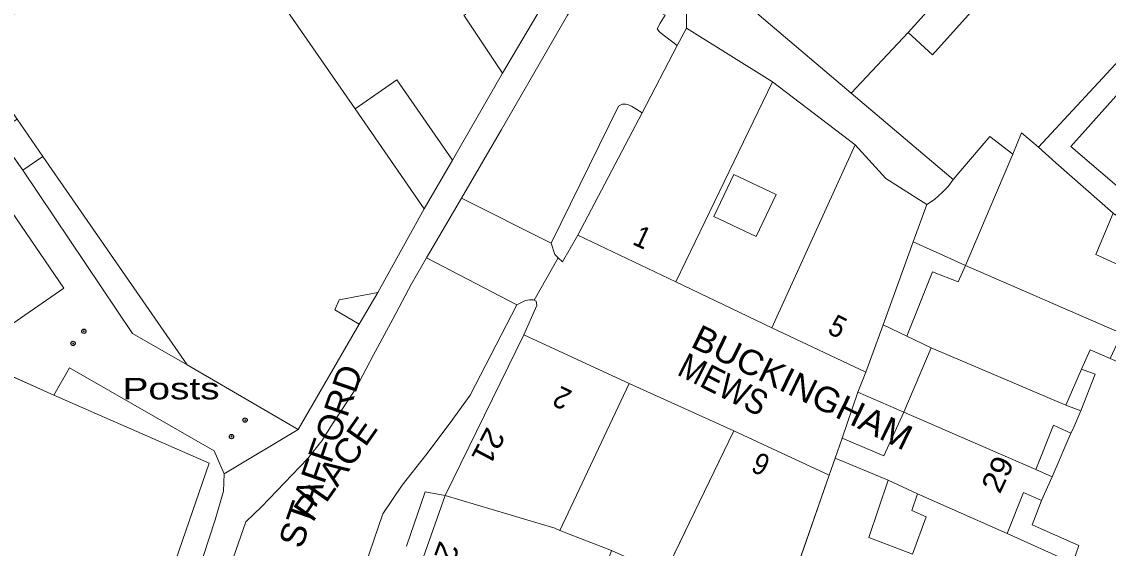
# Model space of a CAD drawing. Extents: x 528790 to 529292, y 179350 to 179856.
# Drawn here: x 529073.1 to 529148.9, y 179462.8 to 179499.5 of the extents above; entities that cross this region are included whole.
import ezdxf

# ---------------------------------------------------------------- set-up
doc = ezdxf.new("R2010")
doc.units = 0
doc.header["$LTSCALE"] = 0.6
doc.header["$PDMODE"] = 32
doc.header["$PDSIZE"] = 0.3
doc.layers.add('1', color=7, linetype='Continuous', lineweight=13)
doc.layers.add('2', color=7, linetype='Continuous', lineweight=13)
doc.layers.add('3', color=7, linetype='Continuous')
doc.layers.add('5', color=7, linetype='Continuous')

msp = doc.modelspace()

# ---------------------------------------------------------------- linework, layer by layer
at = {"layer": '1'}
for points in [[(529146.8, 179512.45), (529154.7, 179521.55), (529151.8, 179524.15), (529145.8, 179529.3), (529145, 179530.05), (529137, 179521.05), (529141.55, 179517.1), (529129.6, 179503.4), (529127.169, 179505.521), (529124.9, 179507.5), (529122.2, 179509.8), (529120.7, 179511.15), (529117.95, 179507.95), (529116.75, 179506.55), (529115.35, 179505), (529119.4, 179501.5), (529120.95, 179503.25), (529124.5, 179500), (529130.929, 179494.567), (529134.9, 179498.8), (529136, 179500)], [(529109, 179500), (529109.35, 179500.6), (529105.55, 179506.3), (529110.55, 179509.6), (529102.9, 179520.85), (529100.55, 179519.25), (529094.1, 179514.85), (529101.27, 179504.213), (529101.65, 179503.65), (529104.05, 179500.05), (529103.9, 179500), (529106.6, 179495.95)], [(529150.25, 179497.55), (529152.55, 179500), (529164.2, 179512.9), (529159.65, 179517), (529154.7, 179521.55), (529146.8, 179512.45), (529148.7, 179510.8), (529139.08, 179500), (529136.6, 179497.25), (529134.9, 179498.8), (529130.929, 179494.567), (529138.05, 179488.55), (529140.6, 179491.55), (529142.2, 179490.3), (529142.8, 179491.8), (529144, 179490.8)], [(529106.6, 179495.95), (529103.9, 179500), (529104.05, 179500.05), (529101.65, 179503.65), (529101.27, 179504.213), (529094.1, 179514.85), (529093.6, 179514.5), (529090.9, 179512.65), (529085.6, 179509), (529091.8, 179500), (529096.316, 179493.479), (529099.225, 179495.494), (529103.106, 179489.891)], [(529146.8, 179512.45), (529136, 179500), (529134.9, 179498.8), (529136.6, 179497.25), (529139.08, 179500), (529148.7, 179510.8)], [(529101.15, 179486.5), (529096.316, 179493.479), (529091.8, 179500), (529085.6, 179509), (529081.6, 179506.25), (529079, 179504.5), (529072.4, 179500), (529069.2, 179497.8), (529072.75, 179492.75), (529074.55, 179490.15), (529084.6, 179475.6), (529092.35, 179471.1), (529096.6, 179478.45), (529094.9, 179479.45), (529095.2, 179480.15), (529097.9, 179480.65)], [(529118.8, 179497.9), (529117.6, 179498.8), (529117.5, 179498.9), (529117.4, 179499.05), (529117.6, 179499.45), (529117.95, 179500), (529113.347, 179502.643), (529112.9, 179502.9), (529111.15, 179500), (529106.544, 179492.033), (529103.74, 179487.23), (529110, 179484.1), (529114.7, 179493.65), (529114.95, 179493.8), (529115.2, 179493.8), (529115.4, 179493.75), (529115.6, 179493.65), (529116.35, 179493.2)], [(529136.75, 179487.15), (529137.25, 179487.6), (529137.7, 179488.05), (529138.05, 179488.55), (529130.929, 179494.567), (529124.5, 179500), (529120.95, 179503.25), (529119.4, 179501.5), (529119.43, 179500), (529119.45, 179499.1), (529125.45, 179495.35), (529131.2, 179490.95), (529133.35, 179488.6), (529136.2, 179486.8)], [(529160.208, 179502.44), (529159.4, 179503.3), (529156.9, 179500.8), (529156.05, 179501.7), (529154.4, 179500), (529151.35, 179496.55), (529147.252, 179491.97), (529146.25, 179490.85), (529150.434, 179487.257), (529150.5, 179487.2), (529154.75, 179492.1), (529155.4, 179491.65), (529158.109, 179494.835), (529155.019, 179497.544), (529156.256, 179499.037), (529156.719, 179498.613)], [(529116.35, 179493.2), (529111.85, 179484.65), (529118.7, 179481.4), (529125.45, 179495.35), (529119.45, 179499.1), (529118.8, 179497.9)], [(529076, 179480.95), (529065.43, 179496.435), (529065.393, 179496.49), (529064.927, 179497.167), (529064.02, 179498.482), (529063.936, 179498.604), (529056.817, 179495.648), (529056.998, 179495.376), (529058.999, 179492.375), (529069.7, 179476.6)], [(529080.8, 179477.8), (529073.15, 179489.2), (529071.25, 179491.85), (529067.05, 179498.1), (529065.393, 179496.49), (529065.43, 179496.435), (529076, 179480.95), (529069.7, 179476.6), (529058.999, 179492.375), (529058.82, 179492.05), (529058.05, 179490.65), (529068.4, 179476.25), (529070.95, 179475.45), (529075.3, 179473.5), (529076.4, 179475.4), (529086.5, 179469.6), (529087.2, 179468), (529092.35, 179471.1), (529084.6, 179475.6)], [(529149.4, 179486.1), (529150.5, 179487.2), (529150.434, 179487.257), (529146.25, 179490.85), (529147.252, 179491.97), (529151.35, 179496.55), (529150.25, 179497.55), (529144, 179490.8), (529145.2, 179489.7), (529149.2, 179486.2), (529149.361, 179486.057)], [(529103.106, 179489.891), (529099.225, 179495.494), (529096.316, 179493.479), (529101.15, 179486.5)], [(529131.2, 179490.95), (529125.45, 179495.35), (529118.7, 179481.4), (529125.4, 179478.2)], [(529111.85, 179484.65), (529116.35, 179493.2), (529115.6, 179493.65), (529115.4, 179493.75), (529115.2, 179493.8), (529114.95, 179493.8), (529114.7, 179493.65), (529110, 179484.1), (529110.25, 179483.3), (529110.5, 179483.07), (529110.8, 179482.8)], [(529071.25, 179491.85), (529073.15, 179489.2), (529074.55, 179490.15), (529072.75, 179492.75)], [(529136.2, 179486.8), (529135.25, 179484.2), (529137.11, 179483.36), (529138.9, 179482.55), (529141.06, 179487.63), (529142.2, 179490.3), (529140.6, 179491.55), (529138.05, 179488.55), (529137.7, 179488.05), (529137.25, 179487.6), (529136.75, 179487.15)], [(529144, 179490.8), (529142.8, 179491.8), (529142.2, 179490.3), (529141.06, 179487.63), (529138.9, 179482.55), (529149.8, 179477.8), (529152.259, 179476.764), (529154.55, 179475.8), (529156.35, 179480), (529152.25, 179483.55), (529151.5, 179481.7), (529148, 179483.3), (529149.2, 179486.2), (529145.2, 179489.7)], [(529125.4, 179478.2), (529131.95, 179475.1), (529133.15, 179478.4), (529135.25, 179484.2), (529136.2, 179486.8), (529133.35, 179488.6), (529131.2, 179490.95)], [(529074.55, 179490.15), (529073.15, 179489.2), (529080.8, 179477.8), (529084.6, 179475.6)], [(529121.353, 179485.965), (529124.301, 179484.565), (529125.695, 179487.499), (529122.747, 179488.899)], [(529121.353, 179485.965), (529122.747, 179488.899), (529125.695, 179487.499), (529124.301, 179484.565)], [(529110.5, 179483.07), (529110.25, 179483.3), (529110, 179484.1), (529103.74, 179487.23), (529102.636, 179485.34), (529101.31, 179483.07), (529107.6, 179479.8), (529108.2, 179480.1), (529108.5, 179480.15), (529108.75, 179480.15), (529108.82, 179480.11)], [(529149.2, 179486.2), (529148, 179483.3), (529151.5, 179481.7), (529152.25, 179483.55), (529151.25, 179484.55), (529149.4, 179486.1), (529149.361, 179486.057)], [(529110.8, 179482.8), (529110.5, 179483.07), (529108.82, 179480.11), (529108.95, 179480.05), (529109, 179479.75), (529108.1, 179477.7), (529115.45, 179474.3), (529122.75, 179471), (529129.4, 179467.9), (529129.8, 179469.1), (529130.3, 179470.5), (529131.4, 179473.7), (529131.95, 179475.1), (529125.4, 179478.2), (529118.7, 179481.4), (529111.85, 179484.65)], [(529134.8, 179477.6), (529136.6, 179482.1), (529138.4, 179481.4), (529138.9, 179482.55), (529137.11, 179483.36), (529135.25, 179484.2), (529133.15, 179478.4)], [(529098.25, 179465.2), (529099.6, 179467.2), (529101.25, 179469.3), (529102.95, 179471.55), (529104.35, 179473.5), (529107.6, 179479.8), (529101.31, 179483.07), (529100.25, 179481.25), (529098.95, 179478.8), (529097.6, 179476.3), (529096.35, 179473.9), (529094.8, 179471.55), (529094, 179470.3), (529093, 179469.05), (529089.8, 179465.7), (529088.7, 179464.65), (529072.2, 179417.3), (529072, 179416.9), (529071.7, 179416.55), (529071.39, 179416.36), (529080.46, 179413.16)], [(529149.8, 179477.8), (529138.9, 179482.55), (529138.4, 179481.4), (529136.6, 179482.1), (529134.8, 179477.6), (529136.5, 179476.8), (529145.9, 179472.8), (529147, 179475.3), (529147.6, 179476.65), (529149, 179476.05)], [(529096.6, 179478.45), (529097.9, 179480.65), (529095.2, 179480.15), (529094.9, 179479.45)], [(529133.15, 179478.4), (529131.95, 179475.1), (529131.4, 179473.7), (529134.6, 179472.3), (529136.5, 179476.8), (529134.8, 179477.6)], [(529102.6, 179466.5), (529110.25, 179464.2), (529110.6, 179464.05), (529115.45, 179474.3), (529108.1, 179477.7)], [(529146.95, 179472.4), (529145.9, 179472.8), (529136.5, 179476.8), (529134.6, 179472.3), (529143.8, 179468.3), (529145.05, 179471.4), (529146.25, 179470.85), (529146.4, 179471.1)], [(529155.75, 179465.25), (529152.8, 179466.55), (529155.7, 179473.15), (529153.7, 179474), (529151.472, 179474.972), (529149, 179476.05), (529147.6, 179476.65), (529147, 179475.3), (529147.95, 179474.95), (529146.95, 179472.4), (529146.4, 179471.1), (529146.25, 179470.85), (529144.95, 179467.8), (529144.2, 179466.15), (529143.55, 179464.45), (529146.8, 179463), (529146.4, 179461.8), (529147, 179461.55), (529153.4, 179460.25)], [(529085.75, 179462.3), (529086.55, 179464.8), (529087.15, 179466.8), (529087.2, 179468), (529086.5, 179469.6), (529076.4, 179475.4), (529075.3, 179473.5), (529086.15, 179468.75), (529068.6, 179417.95), (529070.05, 179417.6)], [(529146.95, 179472.4), (529147.95, 179474.95), (529147, 179475.3), (529145.9, 179472.8)], [(529122.75, 179471), (529115.45, 179474.3), (529110.6, 179464.05), (529114.2, 179462.65), (529117.9, 179461)], [(529131.4, 179473.7), (529130.3, 179470.5), (529133.2, 179469.25), (529134.6, 179472.3)], [(529135.55, 179466.6), (529141.8, 179463.85), (529142.95, 179466.7), (529144.2, 179466.15), (529144.95, 179467.8), (529143.8, 179468.3), (529134.6, 179472.3), (529133.2, 179469.25), (529130.3, 179470.5), (529129.8, 179469.1), (529133.5, 179467.55)], [(529117.9, 179461), (529123, 179458.85), (529125.75, 179457.7), (529126.4, 179459.3), (529129.4, 179467.9), (529122.75, 179471)], [(529143.8, 179468.3), (529144.95, 179467.8), (529146.25, 179470.85), (529145.05, 179471.4)], [(529144.6, 179457.15), (529145.35, 179459.1), (529146.35, 179461.8), (529141.8, 179463.85), (529135.55, 179466.6), (529135.15, 179465.45), (529136.15, 179465), (529135.2, 179462.4), (529132.15, 179463.55), (529133.5, 179467.55), (529129.8, 179469.1), (529129.4, 179467.9), (529126.4, 179459.3), (529130.2, 179457.95), (529131.25, 179460.8), (529134.35, 179459.8), (529133.2, 179456.8), (529143.2, 179453.25)], [(529133.5, 179467.55), (529132.15, 179463.55), (529135.2, 179462.4), (529136.15, 179465), (529135.15, 179465.45), (529135.55, 179466.6)], [(529114.2, 179462.65), (529110.6, 179464.05), (529110.25, 179464.2), (529102.6, 179466.5), (529100.8, 179461.35), (529110.4, 179458.15), (529111.6, 179461.5), (529113.55, 179460.8)], [(529145.35, 179459.1), (529146, 179458.95), (529147, 179461.55), (529146.4, 179461.8), (529146.8, 179463), (529143.55, 179464.45), (529144.2, 179466.15), (529142.95, 179466.7), (529141.8, 179463.85), (529146.35, 179461.8)]]:
    msp.add_lwpolyline(points, close=True, dxfattribs=at)
for points in [[(529114.4, 179506.25), (529113.95, 179506.4), (529113.55, 179506.6), (529113.05, 179506.9), (529109.35, 179500.6), (529109, 179500), (529106.6, 179495.95), (529103.106, 179489.891), (529101.15, 179486.5), (529097.9, 179480.65), (529096.6, 179478.45), (529092.35, 179471.1), (529087.2, 179468), (529087.15, 179466.8), (529086.55, 179464.8), (529085.75, 179462.3), (529070.05, 179417.6)], [(529072.2, 179417.3), (529088.7, 179464.65), (529089.8, 179465.7), (529093, 179469.05), (529094, 179470.3), (529094.8, 179471.55), (529096.35, 179473.9), (529097.6, 179476.3), (529098.95, 179478.8), (529100.25, 179481.25), (529101.31, 179483.07), (529102.636, 179485.34), (529103.74, 179487.23), (529106.544, 179492.033), (529111.15, 179500)], [(529117.95, 179500), (529117.6, 179499.45), (529117.4, 179499.05), (529117.5, 179498.9), (529117.6, 179498.8), (529118.8, 179497.9), (529119.45, 179499.1), (529119.43, 179500)], [(529100.8, 179461.35), (529102.6, 179466.5), (529108.1, 179477.7), (529109, 179479.75), (529108.95, 179480.05), (529108.82, 179480.11), (529108.75, 179480.15), (529108.5, 179480.15), (529108.2, 179480.1), (529107.6, 179479.8), (529104.35, 179473.5), (529102.95, 179471.55), (529101.25, 179469.3), (529099.6, 179467.2), (529098.25, 179465.2), (529080.46, 179413.16)], [(529068.6, 179417.95), (529086.15, 179468.75), (529075.3, 179473.5), (529070.95, 179475.45)]]:
    msp.add_lwpolyline(points, dxfattribs=at)
at = {"layer": '2'}
for p, q in [((529119.45, 179499.1), (529118.8, 179497.9)), ((529125.45, 179495.35), (529119.45, 179499.1)), ((529134.9, 179498.8), (529130.929, 179494.567)), ((529118.8, 179497.9), (529116.35, 179493.2)), ((529144, 179490.8), (529150.25, 179497.55)), ((529103.106, 179489.891), (529106.6, 179495.95)), ((529125.45, 179495.35), (529118.7, 179481.4)), ((529131.2, 179490.95), (529125.45, 179495.35)), ((529130.929, 179494.567), (529138.05, 179488.55)), ((529101.15, 179486.5), (529096.316, 179493.479)), ((529116.35, 179493.2), (529111.85, 179484.65)), ((529072.75, 179492.75), (529074.55, 179490.15)), ((529071.25, 179491.85), (529073.15, 179489.2)), ((529131.2, 179490.95), (529125.4, 179478.2)), ((529073.15, 179489.2), (529074.55, 179490.15)), ((529074.55, 179490.15), (529084.6, 179475.6)), ((529101.15, 179486.5), (529103.106, 179489.891)), ((529110, 179484.1), (529103.74, 179487.23)), ((529135.25, 179484.2), (529136.2, 179486.8)), ((529097.9, 179480.65), (529101.15, 179486.5)), ((529111.85, 179484.65), (529110.8, 179482.8)), ((529111.85, 179484.65), (529118.7, 179481.4)), ((529133.15, 179478.4), (529135.25, 179484.2)), ((529101.31, 179483.07), (529107.6, 179479.8)), ((529110.5, 179483.07), (529108.82, 179480.11)), ((529110.8, 179482.8), (529110.5, 179483.07)), ((529138.9, 179482.55), (529149.8, 179477.8)), ((529118.7, 179481.4), (529125.4, 179478.2)), ((529096.6, 179478.45), (529097.9, 179480.65)), ((529109, 179479.75), (529108.1, 179477.7)), ((529092.35, 179471.1), (529096.6, 179478.45)), ((529131.95, 179475.1), (529133.15, 179478.4)), ((529134.8, 179477.6), (529133.15, 179478.4)), ((529108.1, 179477.7), (529102.6, 179466.5)), ((529115.45, 179474.3), (529108.1, 179477.7)), ((529125.4, 179478.2), (529131.95, 179475.1)), ((529136.5, 179476.8), (529134.8, 179477.6)), ((529134.6, 179472.3), (529136.5, 179476.8)), ((529136.5, 179476.8), (529145.9, 179472.8)), ((529075.3, 179473.5), (529070.95, 179475.45)), ((529084.6, 179475.6), (529092.35, 179471.1)), ((529131.4, 179473.7), (529131.95, 179475.1)), ((529147, 179475.3), (529145.9, 179472.8)), ((529115.45, 179474.3), (529110.6, 179464.05)), ((529122.75, 179471), (529115.45, 179474.3)), ((529130.3, 179470.5), (529131.4, 179473.7)), ((529131.4, 179473.7), (529134.6, 179472.3)), ((529145.9, 179472.8), (529146.95, 179472.4)), ((529134.6, 179472.3), (529143.8, 179468.3)), ((529092.35, 179471.1), (529087.2, 179468)), ((529122.75, 179471), (529117.9, 179461)), ((529129.4, 179467.9), (529122.75, 179471)), ((529146.25, 179470.85), (529144.95, 179467.8)), ((529129.8, 179469.1), (529130.3, 179470.5)), ((529129.8, 179469.1), (529129.4, 179467.9)), ((529133.5, 179467.55), (529129.8, 179469.1)), ((529129.4, 179467.9), (529126.4, 179459.3)), ((529143.8, 179468.3), (529144.95, 179467.8)), ((529144.95, 179467.8), (529144.2, 179466.15)), ((529133.5, 179467.55), (529135.55, 179466.6)), ((529100.8, 179461.35), (529102.6, 179466.5)), ((529141.8, 179463.85), (529135.55, 179466.6)), ((529110.6, 179464.05), (529114.2, 179462.65))]:
    msp.add_line(p, q, dxfattribs=at)
for points in [[(529106.6, 179495.95), (529103.9, 179500), (529104.05, 179500.05), (529101.65, 179503.65), (529101.27, 179504.213), (529094.1, 179514.85)], [(529146.8, 179512.45), (529148.7, 179510.8), (529139.08, 179500), (529136.6, 179497.25), (529134.9, 179498.8)], [(529134.9, 179498.8), (529136, 179500), (529146.8, 179512.45)], [(529085.6, 179509), (529091.8, 179500), (529096.316, 179493.479)], [(529103.74, 179487.23), (529106.544, 179492.033), (529111.15, 179500), (529112.9, 179502.9), (529113.347, 179502.643), (529117.95, 179500), (529117.6, 179499.45), (529117.4, 179499.05), (529117.5, 179498.9), (529117.6, 179498.8), (529118.8, 179497.9)], [(529119.4, 179501.5), (529120.95, 179503.25), (529124.5, 179500), (529130.929, 179494.567)], [(529119.45, 179499.1), (529119.43, 179500), (529119.4, 179501.5)], [(529106.6, 179495.95), (529109, 179500), (529109.35, 179500.6)], [(529058.999, 179492.375), (529069.7, 179476.6), (529076, 179480.95), (529065.43, 179496.435), (529065.393, 179496.49)], [(529150.5, 179487.2), (529150.434, 179487.257), (529146.25, 179490.85), (529147.252, 179491.97), (529151.35, 179496.55)], [(529096.316, 179493.479), (529099.225, 179495.494), (529103.106, 179489.891)], [(529110, 179484.1), (529114.7, 179493.65), (529114.95, 179493.8), (529115.2, 179493.8), (529115.4, 179493.75), (529115.6, 179493.65), (529116.35, 179493.2)], [(529138.05, 179488.55), (529140.6, 179491.55), (529142.2, 179490.3)], [(529144, 179490.8), (529142.8, 179491.8), (529142.2, 179490.3)], [(529136.2, 179486.8), (529133.35, 179488.6), (529131.2, 179490.95)], [(529149.2, 179486.2), (529145.2, 179489.7), (529144, 179490.8)], [(529142.2, 179490.3), (529141.06, 179487.63), (529138.9, 179482.55)], [(529073.15, 179489.2), (529080.8, 179477.8), (529084.6, 179475.6)], [(529136.2, 179486.8), (529136.75, 179487.15), (529137.25, 179487.6), (529137.7, 179488.05), (529138.05, 179488.55)], [(529101.31, 179483.07), (529102.636, 179485.34), (529103.74, 179487.23)], [(529152.25, 179483.55), (529151.5, 179481.7), (529148, 179483.3), (529149.2, 179486.2)], [(529110.5, 179483.07), (529110.25, 179483.3), (529110, 179484.1)], [(529135.25, 179484.2), (529137.11, 179483.36), (529138.9, 179482.55)], [(529071.39, 179416.36), (529071.7, 179416.55), (529072, 179416.9), (529072.2, 179417.3), (529088.7, 179464.65), (529089.8, 179465.7), (529093, 179469.05), (529094, 179470.3), (529094.8, 179471.55), (529096.35, 179473.9), (529097.6, 179476.3), (529098.95, 179478.8), (529100.25, 179481.25), (529101.31, 179483.07)], [(529134.8, 179477.6), (529136.6, 179482.1), (529138.4, 179481.4), (529138.9, 179482.55)], [(529096.6, 179478.45), (529094.9, 179479.45), (529095.2, 179480.15), (529097.9, 179480.65)], [(529107.6, 179479.8), (529108.2, 179480.1), (529108.5, 179480.15), (529108.75, 179480.15), (529108.82, 179480.11)], [(529108.82, 179480.11), (529108.95, 179480.05), (529109, 179479.75)], [(529080.46, 179413.16), (529098.25, 179465.2), (529099.6, 179467.2), (529101.25, 179469.3), (529102.95, 179471.55), (529104.35, 179473.5), (529107.6, 179479.8)], [(529149, 179476.05), (529147.6, 179476.65), (529147, 179475.3)], [(529075.3, 179473.5), (529076.4, 179475.4), (529086.5, 179469.6), (529087.2, 179468)], [(529147, 179475.3), (529147.95, 179474.95), (529146.95, 179472.4)], [(529068.6, 179417.95), (529086.15, 179468.75), (529075.3, 179473.5)], [(529146.95, 179472.4), (529146.4, 179471.1), (529146.25, 179470.85)], [(529130.3, 179470.5), (529133.2, 179469.25), (529134.6, 179472.3)], [(529146.25, 179470.85), (529145.05, 179471.4), (529143.8, 179468.3)], [(529087.2, 179468), (529087.15, 179466.8), (529086.55, 179464.8), (529085.75, 179462.3), (529070.05, 179417.6), (529068.6, 179417.95)], [(529135.55, 179466.6), (529135.15, 179465.45), (529136.15, 179465), (529135.2, 179462.4), (529132.15, 179463.55), (529133.5, 179467.55)], [(529099.9, 179462.95), (529101.2, 179466.75), (529102.6, 179466.5)], [(529102.6, 179466.5), (529110.25, 179464.2), (529110.6, 179464.05)], [(529144.2, 179466.15), (529142.95, 179466.7), (529141.8, 179463.85)], [(529147, 179461.55), (529146.4, 179461.8), (529146.8, 179463), (529143.55, 179464.45), (529144.2, 179466.15)], [(529145.35, 179459.1), (529146.35, 179461.8), (529141.8, 179463.85)]]:
    msp.add_lwpolyline(points, dxfattribs=at)
msp.add_lwpolyline([(529121.353, 179485.965), (529122.747, 179488.899), (529125.695, 179487.499), (529124.301, 179484.565)], close=True, dxfattribs=at)
at = {"layer": '3'}
for p in [(529077.4, 179477.95), (529076.65, 179477.1), (529088.65, 179471.75), (529087.7, 179470.6)]:
    msp.add_point(p, dxfattribs=at)

# ---------------------------------------------------------------- texts
at = {"layer": '5'}
for s, height, rotation, width, p in [('1', 1.5, 335, 0.9, (529115.6, 179484.05)), ('BUCKINGHAM', 1.75, 334, 1.05, (529119.65, 179476.9)), ('5', 1.5, 333, 0.9, (529129.2, 179477.85)), ('MEWS', 1.75, 333, 0.9, (529118.7, 179474.95)), ('STAFFORD', 1.75, 71, 1.05, (529092.6, 179462.7)), ('2', 1.5, 154, 0.9, (529111.54, 179473.74)), ('PLACE', 1.75, 55, 1.05, (529093.35, 179464.55)), ('21', 1.5, 242, 1.1, (529105.54, 179471.35)), ('6', 1.5, 154, 0.9, (529125.41, 179469.13)), ('29', 1.5, 65, 1.1, (529141.3, 179466.55)), ('20', 1.5, 250, 1.1, (529102.23, 179463.4))]:
    msp.add_text(s, height=height, rotation=rotation, dxfattribs=dict(at, width=width)).set_placement(p)
at = {"layer": '5', "width": 1.35}
msp.add_text('Posts', height=1.5, dxfattribs=at).set_placement((529080.1, 179473.2))

doc.saveas('drawing.dxf')
